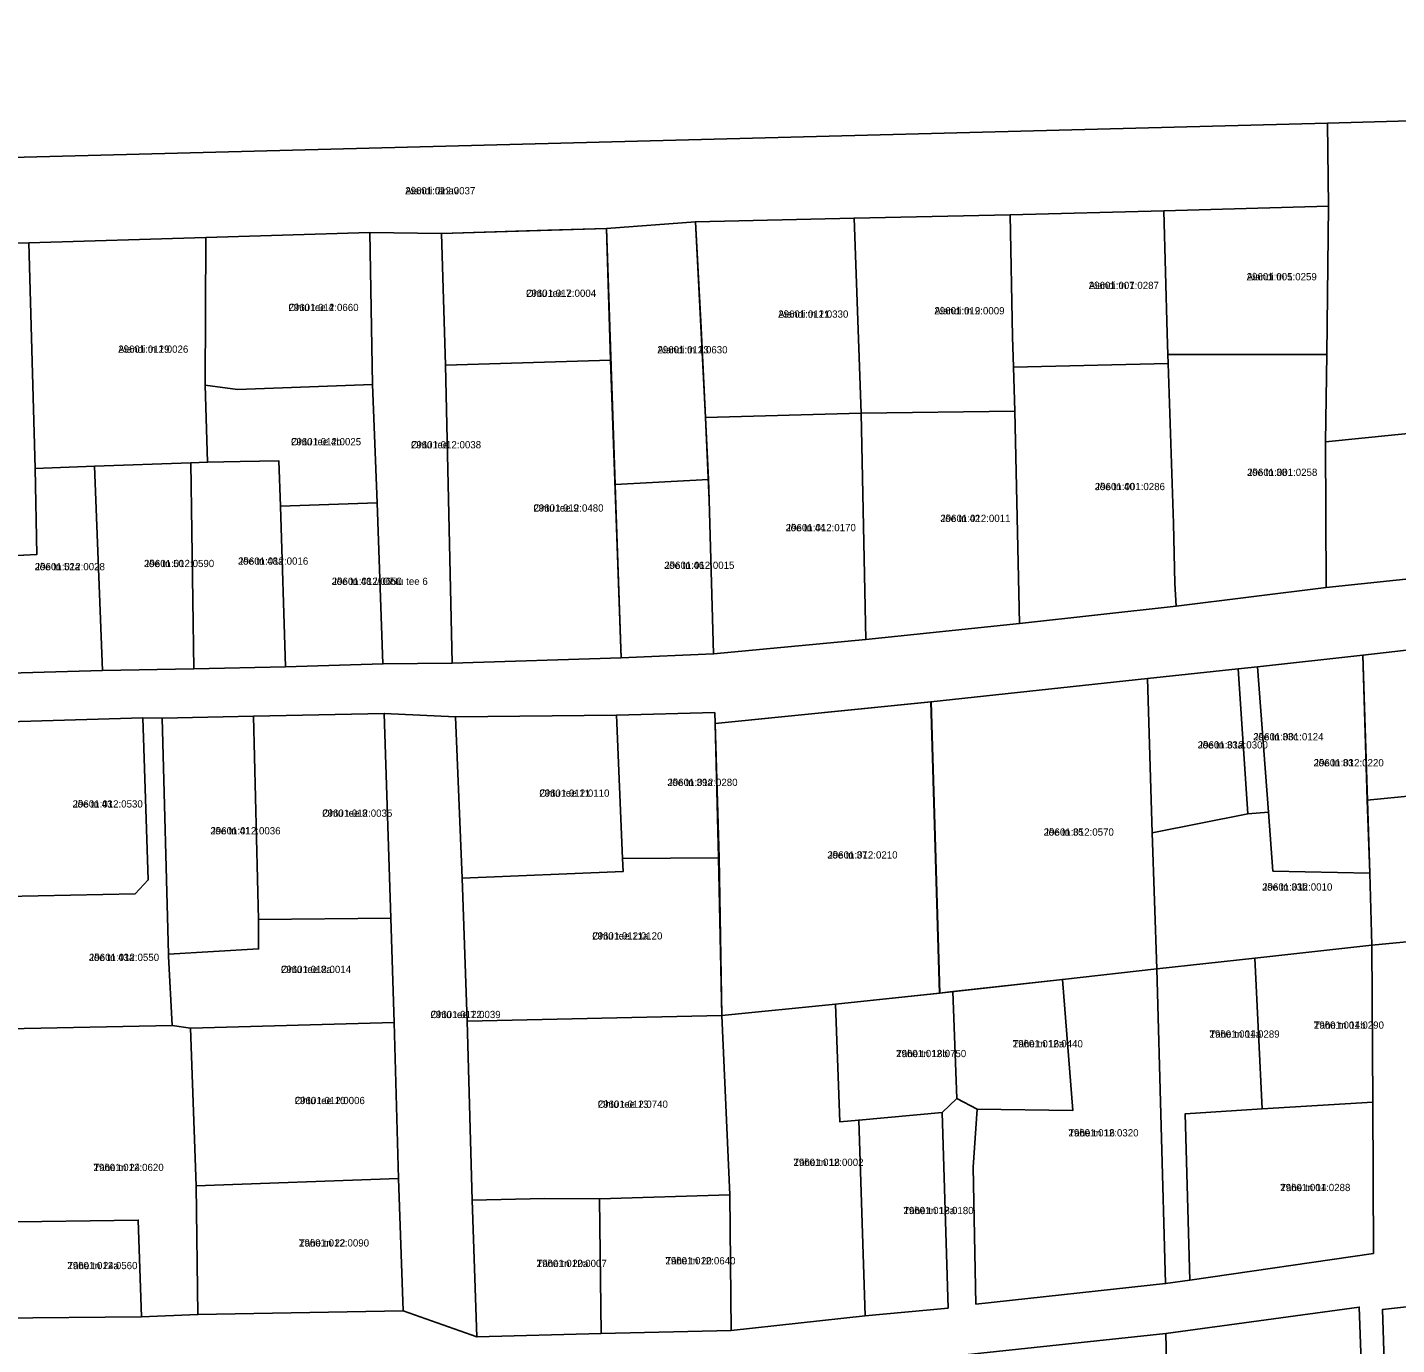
# Model space of a CAD drawing. Extents: x 518839 to 525192, y 6573164 to 6576561.
# Drawn here: x 523676 to 523959.2, y 6574008.4 to 6574281 of the extents above; entities that cross this region are included whole.
import ezdxf

# ---------------------------------------------------------------- set-up
doc = ezdxf.new("R2010")
doc.units = 0
for name, color, linetype in [('L_AADRESS', 7, 'Continuous'), ('PIIR', 7, 'Continuous'), ('TUNNUS', 7, 'Continuous')]:
    doc.layers.add(name, color=color, linetype=linetype)

msp = doc.modelspace()

# ---------------------------------------------------------------- linework, layer by layer
at = {"layer": 'PIIR'}
for points in [[(524245.54, 6574279.22), (524236.65, 6574278.75), (524221.89, 6574280.99), (524188.05, 6574279.68), (524153.11, 6574275.86), (524153.2, 6574268.14), (524136.57, 6574267.06), (524117.88, 6574265.96), (524099.92, 6574265.57), (524072.27, 6574264.7), (524045.04, 6574263.1), (524040.02, 6574262.81), (524014.35, 6574262.2), (523994.2, 6574262), (523978.97, 6574262.1), (523944.89, 6574261.15), (523564.25, 6574251.27), (523514.93, 6574247.34), (523505.75, 6574246.78), (523443.45, 6574245.11), (523380.3, 6574244.03), (523380.42, 6574240.74), (523212.14, 6574237.55)], [(523665, 6574147.15), (523691.49, 6574147.94), (523710.39, 6574148.26), (523729.35, 6574148.65), (523749.53, 6574149.26), (523763.81, 6574149.45), (523798.8, 6574150.54), (523817.89, 6574151.36), (523849.38, 6574154.31), (523881.2, 6574157.67), (523913.54, 6574161.25), (523944.62, 6574165.12), (523979.49, 6574168.72)], [(523972.03, 6574153.38), (523952.16, 6574151.06), (523930.39, 6574148.68), (523926.41, 6574148.26), (523907.67, 6574146.23), (523862.8, 6574141.42), (523818.2, 6574136.97), (523818.15, 6574139.2), (523797.79, 6574138.67), (523764.55, 6574138.34), (523749.78, 6574139.05), (523722.75, 6574138.48), (523703.88, 6574138.08), (523699.86, 6574138.12), (523669.7, 6574137.22)], [(523669.5, 6574013.91), (523699.59, 6574014.19), (523711.27, 6574014.64), (523753.69, 6574015.4), (523768.94, 6574010.01), (523794.66, 6574010.75), (523821.52, 6574011.37), (523849.22, 6574014.39), (523866.41, 6574015.99), (523865.2, 6574056.49), (523868.19, 6574059.35), (523872.44, 6574057.12), (523871.59, 6574045.13), (523872.16, 6574016.83), (523911.39, 6574021.04), (523916.37, 6574021.77), (523954.36, 6574027.29), (523954.21, 6574058.6), (523954.05, 6574091.05), (523961.94, 6574091.83)], [(523979.32, 6574018.22), (523956.21, 6574015.69), (523956.97, 6573992.05)], [(523952.49, 6573986.17), (523951.42, 6574016.19), (523911.44, 6574010.74), (523866.69, 6574005.94)]]:
    msp.add_lwpolyline(points, dxfattribs=at)
for points in [[(523563.13, 6574248.89), (523564.25, 6574251.27), (523944.89, 6574261.15), (523945.07, 6574244.02), (523911.04, 6574243), (523879.26, 6574242.18), (523846.97, 6574241.53), (523814.14, 6574240.78), (523795.74, 6574239.39), (523761.65, 6574238.35), (523746.83, 6574238.52), (523712.92, 6574237.52), (523676.29, 6574236.4), (523633.66, 6574235.41), (523607, 6574234.9), (523586.23, 6574234.21), (523580.31, 6574231.74), (523570.2, 6574233.76), (523563.7, 6574233.58)], [(523978.97, 6574262.1), (523979.23, 6574198.72), (523944.48, 6574195.21), (523944.7, 6574213.27), (523945.07, 6574244.02), (523944.89, 6574261.15)], [(523911.69, 6574217.63), (523911.04, 6574243), (523945.07, 6574244.02), (523944.7, 6574213.27), (523911.82, 6574213.28)], [(523795.74, 6574239.39), (523814.14, 6574240.78), (523815.32, 6574218.83), (523816.25, 6574200.25), (523816.83, 6574187.46), (523797.53, 6574186.4)], [(523846.97, 6574241.53), (523848.4, 6574201.13), (523816.25, 6574200.25), (523814.14, 6574240.78)], [(523879.26, 6574242.18), (523879.73, 6574216.97), (523879.95, 6574210.7), (523880.17, 6574201.58), (523848.4, 6574201.13), (523846.97, 6574241.53)], [(523879.73, 6574216.97), (523879.26, 6574242.18), (523911.04, 6574243), (523911.69, 6574217.63), (523911.82, 6574213.28), (523911.89, 6574211.41), (523879.95, 6574210.7)], [(523746.83, 6574238.52), (523747.39, 6574207.09), (523719.42, 6574206.06), (523712.78, 6574206.93), (523712.92, 6574237.52)], [(523746.83, 6574238.52), (523761.65, 6574238.35), (523762.49, 6574211.06), (523763.81, 6574149.45), (523749.53, 6574149.26), (523748.32, 6574182.61), (523747.39, 6574207.09)], [(523783.64, 6574239.02), (523795.74, 6574239.39), (523796.57, 6574212.1), (523762.49, 6574211.06), (523761.65, 6574238.35)], [(523633.66, 6574235.41), (523676.29, 6574236.4), (523677.57, 6574189.74), (523677.96, 6574171.95), (523635.17, 6574169.77), (523634.79, 6574189.47)], [(523676.29, 6574236.4), (523712.92, 6574237.52), (523712.78, 6574206.93), (523713.25, 6574190.99), (523709.78, 6574190.89), (523689.85, 6574190.17), (523677.57, 6574189.74)], [(523913.01, 6574178.36), (523911.89, 6574211.41), (523911.82, 6574213.28), (523944.7, 6574213.27), (523944.48, 6574195.21), (523944.62, 6574165.12), (523913.54, 6574161.25), (523913.28, 6574165.94)], [(523762.49, 6574211.06), (523796.57, 6574212.1), (523798.8, 6574150.54), (523763.81, 6574149.45)], [(523880.17, 6574201.58), (523879.95, 6574210.7), (523911.89, 6574211.41), (523913.01, 6574178.36), (523913.28, 6574165.94), (523913.54, 6574161.25), (523881.2, 6574157.67)], [(523712.78, 6574206.93), (523719.42, 6574206.06), (523747.39, 6574207.09), (523748.32, 6574182.61), (523728.35, 6574181.93), (523727.96, 6574191.32), (523719.98, 6574191.19), (523713.25, 6574190.99)], [(523848.4, 6574201.13), (523849.38, 6574154.31), (523817.89, 6574151.36), (523817.02, 6574183.16), (523816.25, 6574200.25)], [(523848.4, 6574201.13), (523880.17, 6574201.58), (523881.2, 6574157.67), (523849.38, 6574154.31)], [(523944.48, 6574195.21), (523979.23, 6574198.72), (523979.49, 6574168.72), (523944.62, 6574165.12)], [(523677.57, 6574189.74), (523689.85, 6574190.17), (523691.49, 6574147.94), (523665, 6574147.15), (523664.28, 6574171.25), (523677.96, 6574171.95)], [(523689.85, 6574190.17), (523709.78, 6574190.89), (523710.39, 6574148.26), (523691.49, 6574147.94)], [(523709.78, 6574190.89), (523713.25, 6574190.99), (523719.98, 6574191.19), (523727.96, 6574191.32), (523728.35, 6574181.93), (523729.35, 6574148.65), (523710.39, 6574148.26)], [(523797.53, 6574186.4), (523816.83, 6574187.46), (523817.02, 6574183.16), (523817.89, 6574151.36), (523798.8, 6574150.54), (523797.67, 6574182.1)], [(523748.32, 6574182.61), (523749.53, 6574149.26), (523729.35, 6574148.65), (523728.35, 6574181.93)], [(523972.03, 6574153.38), (523972.8, 6574123), (523953.06, 6574121.1), (523952.16, 6574151.06)], [(523932.66, 6574118.57), (523930.39, 6574148.68), (523952.16, 6574151.06), (523953.6, 6574105.96), (523933.57, 6574106.4)], [(523907.67, 6574146.23), (523926.41, 6574148.26), (523928.38, 6574118.25), (523908.63, 6574114.34)], [(523928.38, 6574118.25), (523926.41, 6574148.26), (523930.39, 6574148.68), (523932.66, 6574118.57)], [(523862.8, 6574141.42), (523907.67, 6574146.23), (523908.63, 6574114.34), (523909.57, 6574086.17), (523890.06, 6574083.98), (523864.61, 6574081.17)], [(523722.75, 6574138.48), (523749.78, 6574139.05), (523751.17, 6574096.69), (523723.78, 6574096.37)], [(523749.78, 6574139.05), (523764.55, 6574138.34), (523765.89, 6574104.91), (523766.93, 6574075.32), (523767.97, 6574038.33), (523768.94, 6574010.01), (523753.69, 6574015.4), (523752.71, 6574042.8), (523751.81, 6574075.09), (523751.17, 6574096.69)], [(523764.55, 6574138.34), (523797.79, 6574138.67), (523799.05, 6574109.01), (523799.17, 6574106.29), (523765.89, 6574104.91)], [(523818.15, 6574139.2), (523818.2, 6574136.97), (523818.94, 6574109.17), (523799.05, 6574109.01), (523797.79, 6574138.67)], [(523819.03, 6574109.18), (523818.2, 6574136.97), (523862.89, 6574141.43), (523864.7, 6574081.18), (523843.12, 6574078.89), (523819.59, 6574076.53)], [(523671.15, 6574106.4), (523671.04, 6574108.77), (523669.7, 6574137.22), (523699.86, 6574138.12), (523700.99, 6574104.58), (523698.26, 6574101.72), (523671.54, 6574101.12)], [(523671.54, 6574101.12), (523698.26, 6574101.72), (523700.99, 6574104.58), (523699.86, 6574138.12), (523703.88, 6574138.08), (523705.14, 6574089.19), (523705.16, 6574088.83), (523705.92, 6574074.48), (523671.96, 6574073.75)], [(523703.88, 6574138.08), (523722.75, 6574138.48), (523723.78, 6574096.37), (523723.81, 6574090.3), (523705.14, 6574089.19)], [(523953.06, 6574121.1), (523972.8, 6574123), (523973.87, 6574092.91), (523961.94, 6574091.83), (523954.05, 6574091.05), (523953.6, 6574105.96)], [(523908.63, 6574114.34), (523928.38, 6574118.25), (523932.66, 6574118.57), (523933.57, 6574106.4), (523953.6, 6574105.96), (523954.05, 6574091.05), (523929.86, 6574088.4), (523909.57, 6574086.17)], [(523765.89, 6574104.91), (523799.17, 6574106.29), (523799.05, 6574109.01), (523818.94, 6574109.17), (523819.59, 6574076.53), (523766.93, 6574075.32)], [(523705.14, 6574089.19), (523723.81, 6574090.3), (523723.78, 6574096.37), (523751.17, 6574096.69), (523751.81, 6574075.09), (523709.69, 6574073.94), (523705.92, 6574074.48), (523705.16, 6574088.83)], [(523931.34, 6574057.19), (523929.86, 6574088.4), (523954.05, 6574091.05), (523954.21, 6574058.6)], [(523911.39, 6574021.04), (523909.57, 6574086.17), (523929.86, 6574088.4), (523931.34, 6574057.19), (523915.46, 6574056.21), (523916.37, 6574021.77)], [(523871.59, 6574045.13), (523872.44, 6574057.12), (523892.17, 6574056.84), (523890.06, 6574083.98), (523909.57, 6574086.17), (523911.39, 6574021.04), (523872.16, 6574016.83)], [(523890.06, 6574083.98), (523892.17, 6574056.84), (523872.44, 6574057.12), (523868.19, 6574059.35), (523867.36, 6574081.47)], [(523847.93, 6574054.87), (523844.04, 6574054.5), (523843.12, 6574078.89), (523864.61, 6574081.17), (523867.36, 6574081.47), (523868.19, 6574059.35), (523865.2, 6574056.49)], [(523766.93, 6574075.32), (523819.59, 6574076.53), (523821.29, 6574039.42), (523794.33, 6574038.57), (523782.9, 6574038.63), (523767.97, 6574038.33)], [(523821.29, 6574039.42), (523819.59, 6574076.53), (523843.12, 6574078.89), (523844.04, 6574054.5), (523847.93, 6574054.87), (523849.22, 6574014.39), (523821.52, 6574011.37)], [(523667.24, 6574073.44), (523671.96, 6574073.75), (523705.92, 6574074.48), (523709.69, 6574073.94), (523710.92, 6574041.29), (523711.27, 6574014.64), (523699.59, 6574014.19), (523698.91, 6574034.18), (523669, 6574033.75)], [(523751.81, 6574075.09), (523752.71, 6574042.8), (523710.92, 6574041.29), (523709.69, 6574073.94)], [(523916.37, 6574021.77), (523915.46, 6574056.21), (523931.34, 6574057.19), (523954.21, 6574058.6), (523954.36, 6574027.29)], [(523849.22, 6574014.39), (523847.93, 6574054.87), (523865.2, 6574056.49), (523866.41, 6574015.99)], [(523710.92, 6574041.29), (523752.71, 6574042.8), (523753.69, 6574015.4), (523711.27, 6574014.64)], [(523782.9, 6574038.63), (523794.33, 6574038.57), (523794.66, 6574010.75), (523768.94, 6574010.01), (523767.97, 6574038.33)], [(523821.29, 6574039.42), (523821.52, 6574011.37), (523794.66, 6574010.75), (523794.33, 6574038.57)], [(523669, 6574033.75), (523698.91, 6574034.18), (523699.59, 6574014.19), (523669.5, 6574013.91)], [(523956.21, 6574015.69), (523979.32, 6574018.22), (523980.25, 6573991.75), (523956.97, 6573992.05)], [(523912.33, 6573972.02), (523911.44, 6574010.74), (523951.42, 6574016.19), (523952.49, 6573986.17), (523937.04, 6573984.67), (523938.18, 6573953.35), (523933.24, 6573953.09), (523932.55, 6573968.95), (523912.44, 6573967.71)], [(523867.49, 6573988.11), (523866.69, 6574005.94), (523911.44, 6574010.74), (523912.33, 6573972.02), (523897.81, 6573971.55), (523868.11, 6573969.95), (523867.78, 6573979.24)]]:
    msp.add_lwpolyline(points, close=True, dxfattribs=at)

# ---------------------------------------------------------------- texts
at = {"layer": 'L_AADRESS'}
for s, p in [('Aiandi tänav', (523754.13, 6574246.44)), ('Aiandi tn 5', (523928.15, 6574228.65)), ('Ohtu tee 7', (523779.11, 6574225.23)), ('Aiandi tn 7', (523895.5, 6574226.85)), ('Ohtu tee 4', (523729.98, 6574222.29)), ('Aiandi tn 11', (523831.27, 6574220.92)), ('Aiandi tn 9', (523863.57, 6574221.6)), ('Aiandi tn 19', (523694.77, 6574213.66)), ('Aiandi tn 13', (523806.29, 6574213.53)), ('Ohtu tee 4b', (523730.51, 6574194.51)), ('Ohtu tee', (523755.32, 6574193.88)), ('Jõe tn 38', (523928.26, 6574188.18)), ('Jõe tn 40', (523896.75, 6574185.23)), ('Ohtu tee 9', (523780.64, 6574180.79)), ('Jõe tn 44', (523832.82, 6574176.73)), ('Jõe tn 42', (523864.8, 6574178.65)), ('Jõe tn 52a', (523677.52, 6574168.66)), ('Jõe tn 50', (523700.12, 6574169.31)), ('Jõe tn 48a', (523719.57, 6574169.81)), ('Jõe tn 46', (523807.71, 6574168.94)), ('Jõe tn 48 // Ohtu tee 6', (523738.94, 6574165.62)), ('Jõe tn 33a', (523918.03, 6574131.78)), ('Jõe tn 33c', (523929.53, 6574133.46)), ('Jõe tn 33', (523942, 6574128.08)), ('Jõe tn 39a', (523808.36, 6574124.02)), ('Ohtu tee 11', (523781.86, 6574121.79)), ('Jõe tn 43', (523685.35, 6574119.56)), ('Ohtu tee 8', (523736.96, 6574117.65)), ('Jõe tn 41', (523713.85, 6574114)), ('Jõe tn 35', (523886.18, 6574113.74)), ('Jõe tn 37', (523841.45, 6574109.01)), ('Jõe tn 33b', (523931.37, 6574102.37)), ('Ohtu tee 11a', (523792.81, 6574092.25)), ('Jõe tn 43a', (523688.73, 6574087.81)), ('Ohtu tee 8a', (523728.43, 6574085.32)), ('Ohtu tee T2', (523759.36, 6574075.99)), ('Tähe tn 14a', (523920.46, 6574071.94)), ('Tähe tn 14b', (523942.04, 6574073.79)), ('Tähe tn 16a', (523879.77, 6574069.93)), ('Tähe tn 18b', (523855.65, 6574067.91)), ('Ohtu tee 10', (523731.28, 6574058.19)), ('Ohtu tee 13', (523793.95, 6574057.43)), ('Tähe tn 16', (523891.29, 6574051.5)), ('Tähe tn 24', (523689.67, 6574044.34)), ('Tähe tn 18', (523834.41, 6574045.4)), ('Tähe tn 14', (523935.09, 6574040.19)), ('Tähe tn 18a', (523857.17, 6574035.43)), ('Tähe tn 22', (523732.15, 6574028.72)), ('Tähe tn 24a', (523684.25, 6574024.04)), ('Tähe tn 20a', (523781.31, 6574024.48)), ('Tähe tn 20', (523807.93, 6574025.03))]:
    msp.add_text(s, height=1.5, dxfattribs=at).set_placement(p)
at = {"layer": 'TUNNUS'}
for s, p in [('29601:012:0037', (523754.13, 6574246.44)), ('29601:001:0259', (523928.15, 6574228.65)), ('29601:012:0004', (523779.11, 6574225.23)), ('29601:001:0287', (523895.5, 6574226.85)), ('29601:012:0660', (523729.98, 6574222.29)), ('29601:012:0330', (523831.27, 6574220.92)), ('29601:012:0009', (523863.57, 6574221.6)), ('29601:012:0026', (523694.77, 6574213.66)), ('29601:012:0630', (523806.29, 6574213.53)), ('29601:012:0025', (523730.51, 6574194.51)), ('29601:012:0038', (523755.32, 6574193.88)), ('29601:001:0258', (523928.26, 6574188.18)), ('29601:001:0286', (523896.75, 6574185.23)), ('29601:012:0480', (523780.64, 6574180.79)), ('29601:012:0011', (523864.8, 6574178.65)), ('29601:012:0170', (523832.82, 6574176.73)), ('29601:012:0028', (523677.52, 6574168.66)), ('29601:012:0590', (523700.12, 6574169.31)), ('29601:012:0016', (523719.57, 6574169.81)), ('29601:012:0015', (523807.71, 6574168.94)), ('29601:012:0650', (523738.94, 6574165.62)), ('29601:012:0300', (523918.03, 6574131.78)), ('29601:001:0124', (523929.53, 6574133.46)), ('29601:012:0220', (523942, 6574128.08)), ('29601:012:0280', (523808.36, 6574124.02)), ('29601:012:0110', (523781.86, 6574121.79)), ('29601:012:0530', (523685.35, 6574119.56)), ('29601:012:0035', (523736.96, 6574117.65)), ('29601:012:0036', (523713.85, 6574114)), ('29601:012:0570', (523886.18, 6574113.74)), ('29601:012:0210', (523841.45, 6574109.01)), ('29601:012:0010', (523931.37, 6574102.37)), ('29601:012:0120', (523792.81, 6574092.25)), ('29601:012:0550', (523688.73, 6574087.81)), ('29601:012:0014', (523728.43, 6574085.32)), ('29601:012:0039', (523759.36, 6574075.99)), ('29601:001:0290', (523942.04, 6574073.79)), ('29601:012:0440', (523879.77, 6574069.93)), ('29601:001:0289', (523920.46, 6574071.94)), ('29601:012:0750', (523855.65, 6574067.91)), ('29601:012:0006', (523731.28, 6574058.19)), ('29601:012:0740', (523793.95, 6574057.43)), ('29601:012:0320', (523891.29, 6574051.5)), ('29601:012:0620', (523689.67, 6574044.34)), ('29601:012:0002', (523834.41, 6574045.4)), ('29601:001:0288', (523935.09, 6574040.19)), ('29601:012:0180', (523857.17, 6574035.43)), ('29601:012:0090', (523732.15, 6574028.72)), ('29601:012:0560', (523684.25, 6574024.04)), ('29601:012:0007', (523781.31, 6574024.48)), ('29601:012:0640', (523807.93, 6574025.03))]:
    msp.add_text(s, height=1.5, dxfattribs=at).set_placement(p)

doc.saveas('drawing.dxf')
